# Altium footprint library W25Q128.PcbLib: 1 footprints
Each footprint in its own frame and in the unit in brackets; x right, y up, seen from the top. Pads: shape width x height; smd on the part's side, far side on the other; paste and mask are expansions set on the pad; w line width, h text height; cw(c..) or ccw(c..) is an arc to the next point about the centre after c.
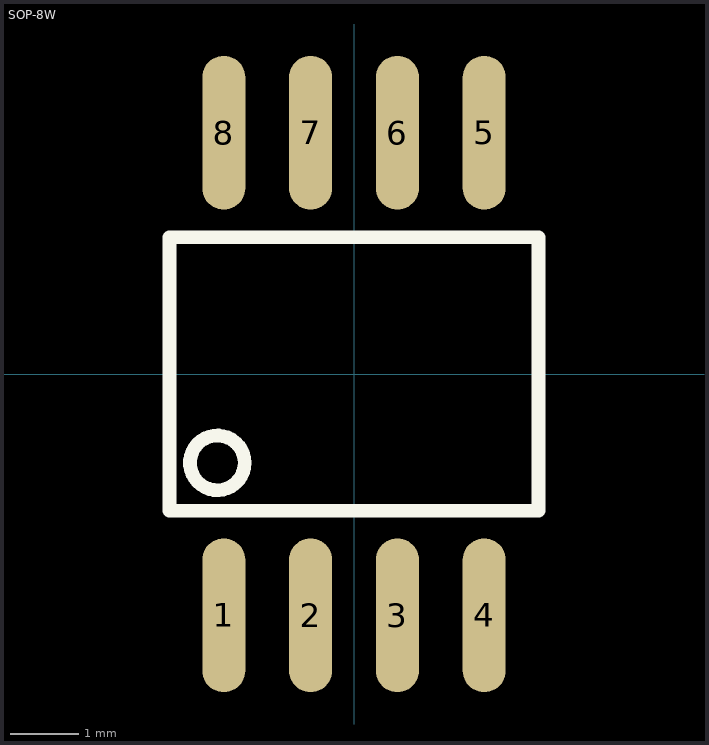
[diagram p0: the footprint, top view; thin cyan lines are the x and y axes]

## SOP-8W [mm]
pads (8):
  oval 0.63x2.25 smd mask+0.05: 1(-1.905,-3.53) 2(-0.635,-3.53) 3(0.635,-3.53) 4(1.905,-3.53) 5(1.905,3.53) 6(0.635,3.53) 7(-0.635,3.53) 8(-1.905,3.53)
Top Overlay:
  circle w0.2: c-2,-1.3 r0.4
  lines w0.2: -2.7,-2 -2.7,2 2.7,2 2.7,-2 -2.7,-2
3D body "SOIC-8_L5.3-W5.3-P1.27-LS8.2-BL.step": height 1.89, standoff -0.04, extent -2.62,-3.99 2.62,3.99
